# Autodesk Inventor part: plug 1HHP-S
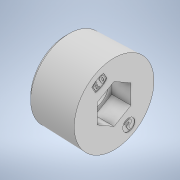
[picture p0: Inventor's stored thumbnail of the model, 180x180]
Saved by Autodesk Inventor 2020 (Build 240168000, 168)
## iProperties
Created: 2019-12
Part Number: plug 1HHP-S
Material: Generico
Description: STEP AP203
Document SubType Name: Modeling
Designer: carlo
Density: 1 g/cm^3
Appearance: Default
DataBaseUnit: MM
Title: p:/temp/worker_141/temp/exporttempdir_1132_809_X1ckb/format_0/Adapters Hexagon socket plug 1HHP-S.stp
Revision Number: NONE
Sending System: PARTsolutions
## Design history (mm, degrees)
feature "_Adapters Hexagon socket plug 1HHP-S"
node "Solido1"
